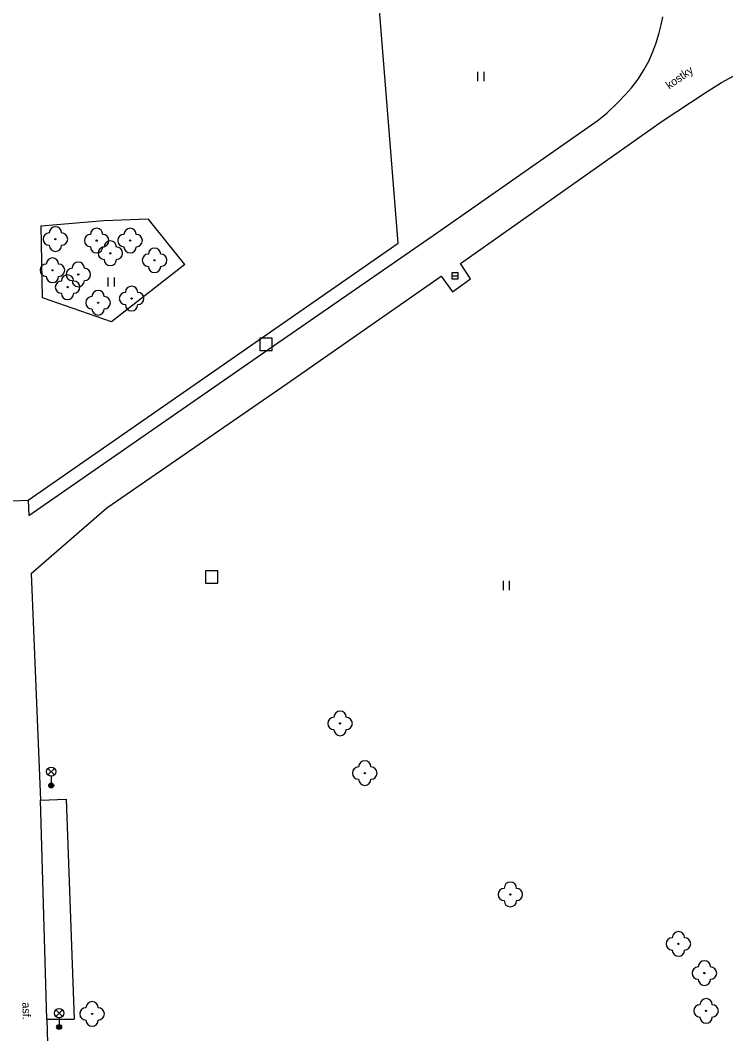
# Model space of a CAD drawing. Extents: x -641829 to -641525, y -1114855 to -1114359.
# Drawn here: x -641652.8 to -641595.5, y -1114618.1 to -1114535.8 of the extents above; entities that cross this region are included whole.
import ezdxf

# ---------------------------------------------------------------- set-up
doc = ezdxf.new("R2010")
doc.units = 0
for name, color, linetype in [('Vrstva 10', 7, 'Continuous'), ('Vrstva 11', 7, 'Continuous'), ('Vrstva 22', 7, 'Continuous'), ('Vrstva 26', 7, 'Continuous'), ('Vrstva 27', 7, 'Continuous'), ('Vrstva 33', 7, 'Continuous'), ('Vrstva 36', 7, 'Continuous'), ('Vrstva 40', 7, 'Continuous')]:
    doc.layers.add(name, color=color, linetype=linetype)

msp = doc.modelspace()

# ---------------------------------------------------------------- linework, layer by layer
at = {"layer": 'Vrstva 10'}
for p, q in [((-641622.14, -1114553.93), (-641623.76, -1114533.67)), ((-641651.12, -1114552.53), (-641646.05, -1114552.1)), ((-641646.05, -1114552.1), (-641642.43, -1114551.97)), ((-641639.45, -1114555.68), (-641642.43, -1114551.97)), ((-641651.01, -1114558.37), (-641651.12, -1114552.53)), ((-641652.17, -1114574.8), (-641622.14, -1114553.93)), ((-641639.45, -1114555.68), (-641645.42, -1114560.33)), ((-641645.42, -1114560.33), (-641651.01, -1114558.37)), ((-641655.53, -1114574.94), (-641652.17, -1114574.8))]:
    msp.add_line(p, q, dxfattribs=at)
at = {"layer": 'Vrstva 11'}
for p, q in [((-641600.78, -1114536.22), (-641600.64, -1114535.57)), ((-641600.93, -1114536.85), (-641600.78, -1114536.22)), ((-641601.19, -1114537.75), (-641600.93, -1114536.85)), ((-641601.46, -1114538.46), (-641601.19, -1114537.75)), ((-641601.76, -1114539.15), (-641601.46, -1114538.46)), ((-641602.64, -1114540.61), (-641602.21, -1114539.92)), ((-641602.21, -1114539.92), (-641601.76, -1114539.15)), ((-641603.18, -1114541.33), (-641602.64, -1114540.61)), ((-641595.87, -1114540.89), (-641594.56, -1114540.18)), ((-641603.67, -1114541.88), (-641603.18, -1114541.33)), ((-641597.19, -1114541.72), (-641595.87, -1114540.89)), ((-641604.35, -1114542.58), (-641603.67, -1114541.88)), ((-641600.69, -1114544.03), (-641597.19, -1114541.72)), ((-641605.19, -1114543.37), (-641604.35, -1114542.58)), ((-641618.94, -1114553.06), (-641605.89, -1114543.94)), ((-641617.07, -1114555.58), (-641600.69, -1114544.03)), ((-641605.89, -1114543.94), (-641605.19, -1114543.37)), ((-641632.62, -1114562.53), (-641618.94, -1114553.06)), ((-641616.26, -1114556.83), (-641617.07, -1114555.58)), ((-641631.15, -1114565.34), (-641618.63, -1114556.62)), ((-641618.63, -1114556.62), (-641617.72, -1114557.88)), ((-641617.72, -1114557.88), (-641616.26, -1114556.83)), ((-641652.12, -1114576.06), (-641632.62, -1114562.53)), ((-641645.8, -1114575.42), (-641631.15, -1114565.34)), ((-641652.17, -1114574.8), (-641652.12, -1114576.06)), ((-641651.93, -1114580.76), (-641645.8, -1114575.42)), ((-641651.93, -1114580.76), (-641651.19, -1114599.17)), ((-641651.19, -1114599.17), (-641649.1, -1114599.09)), ((-641650.66, -1114616.94), (-641651.19, -1114599.17)), ((-641649.1, -1114599.09), (-641648.45, -1114616.94)), ((-641650.66, -1114616.94), (-641650.62, -1114618.87)), ((-641650.66, -1114616.94), (-641648.45, -1114616.94))]:
    msp.add_line(p, q, dxfattribs=at)
at = {"layer": 'Vrstva 22'}
for centre in [(-641649.97, -1114553.61), (-641646.62, -1114553.73), (-641643.9, -1114553.73), (-641645.51, -1114554.76), (-641641.92, -1114555.33), (-641650.21, -1114556.14), (-641648.11, -1114556.48), (-641648.98, -1114557.51), (-641646.5, -1114558.77), (-641643.78, -1114558.43), (-641626.85, -1114592.93), (-641624.84, -1114596.96), (-641613.02, -1114606.82), (-641599.37, -1114610.83), (-641597.26, -1114613.2), (-641597.12, -1114616.27), (-641646.99, -1114616.52)]:
    msp.add_circle(centre, 0.05, dxfattribs=at)
for centre, start, end in [((-641649.97, -1114553.11), 0, 180), ((-641646.62, -1114553.23), 0, 180), ((-641643.9, -1114553.23), 0, 180), ((-641650.47, -1114553.61), 90, 270), ((-641649.47, -1114553.61), 270, 90), ((-641647.12, -1114553.73), 90, 270), ((-641646.12, -1114553.73), 270, 90), ((-641645.51, -1114554.26), 0, 180), ((-641644.4, -1114553.73), 90, 270), ((-641643.4, -1114553.73), 270, 90), ((-641649.97, -1114554.11), 180, 0), ((-641646.62, -1114554.23), 180, 0), ((-641646.01, -1114554.76), 90, 270), ((-641645.01, -1114554.76), 270, 90), ((-641643.9, -1114554.23), 180, 0), ((-641641.92, -1114554.83), 0, 180), ((-641650.21, -1114555.64), 0, 180), ((-641648.11, -1114555.98), 0, 180), ((-641645.51, -1114555.26), 180, 0), ((-641642.42, -1114555.33), 90, 270), ((-641641.42, -1114555.33), 270, 90), ((-641650.71, -1114556.14), 90, 270), ((-641649.71, -1114556.14), 270, 90), ((-641648.61, -1114556.48), 90, 270), ((-641647.61, -1114556.48), 270, 90), ((-641641.92, -1114555.83), 180, 0), ((-641650.21, -1114556.64), 180, 0), ((-641649.48, -1114557.51), 90, 270), ((-641648.98, -1114557.01), 0, 180), ((-641648.11, -1114556.98), 180, 0), ((-641648.48, -1114557.51), 270, 90), ((-641648.98, -1114558.01), 180, 0), ((-641646.5, -1114558.27), 0, 180), ((-641644.28, -1114558.43), 90, 270), ((-641643.78, -1114557.93), 0, 180), ((-641643.28, -1114558.43), 270, 90), ((-641647, -1114558.77), 90, 270), ((-641646, -1114558.77), 270, 90), ((-641646.5, -1114559.27), 180, 0), ((-641643.78, -1114558.93), 180, 0), ((-641627.35, -1114592.93), 90, 270), ((-641626.85, -1114592.43), 0, 180), ((-641626.35, -1114592.93), 270, 90), ((-641626.85, -1114593.43), 180, 0), ((-641625.34, -1114596.96), 90, 270), ((-641624.84, -1114596.46), 0, 180), ((-641624.34, -1114596.96), 270, 90), ((-641624.84, -1114597.46), 180, 0), ((-641613.52, -1114606.82), 90, 270), ((-641613.02, -1114606.32), 0, 180), ((-641612.52, -1114606.82), 270, 90), ((-641613.02, -1114607.32), 180, 0), ((-641599.37, -1114610.33), 0, 180), ((-641599.87, -1114610.83), 90, 270), ((-641598.87, -1114610.83), 270, 90), ((-641599.37, -1114611.33), 180, 0), ((-641597.26, -1114612.7), 0, 180), ((-641597.76, -1114613.2), 90, 270), ((-641596.76, -1114613.2), 270, 90), ((-641597.26, -1114613.7), 180, 0), ((-641646.99, -1114616.02), 0, 180), ((-641597.12, -1114615.77), 0, 180), ((-641647.49, -1114616.52), 90, 270), ((-641646.49, -1114616.52), 270, 90), ((-641597.62, -1114616.27), 90, 270), ((-641596.62, -1114616.27), 270, 90), ((-641646.99, -1114617.02), 180, 0), ((-641597.12, -1114616.77), 180, 0)]:
    msp.add_arc(centre, 0.5, start, end, dxfattribs=at)
at = {"layer": 'Vrstva 26'}
for points in [[(-641633.36, -1114562.65), (-641632.36, -1114562.65), (-641632.36, -1114561.65), (-641633.36, -1114561.65)], [(-641637.79, -1114581.54), (-641636.79, -1114581.54), (-641636.79, -1114580.54), (-641637.79, -1114580.54)]]:
    msp.add_lwpolyline(points, close=True, dxfattribs=at)
at = {"layer": 'Vrstva 27'}
msp.add_line((-641617.76, -1114556.59), (-641617.26, -1114556.59), dxfattribs=at)
msp.add_lwpolyline([(-641617.76, -1114556.84), (-641617.26, -1114556.84), (-641617.26, -1114556.34), (-641617.76, -1114556.34)], close=True, dxfattribs=at)
at = {"layer": 'Vrstva 33'}
for p, q in [((-641650.574, -1114597.11), (-641650.046, -1114596.58)), ((-641650.574, -1114596.58), (-641650.046, -1114597.11)), ((-641650.31, -1114597.22), (-641650.31, -1114597.97)), ((-641649.936, -1114616.72), (-641649.404, -1114616.19)), ((-641649.936, -1114616.19), (-641649.404, -1114616.72)), ((-641649.67, -1114616.83), (-641649.67, -1114617.58))]:
    msp.add_line(p, q, dxfattribs=at)
for centre, radius in [((-641650.31, -1114596.845), 0.375), ((-641650.31, -1114597.97), 0.2), ((-641650.31, -1114597.97), 0.145), ((-641650.31, -1114597.97), 0.0876), ((-641649.67, -1114616.455), 0.375), ((-641649.67, -1114617.58), 0.2), ((-641649.67, -1114617.58), 0.145), ((-641649.67, -1114617.58), 0.0876)]:
    msp.add_circle(centre, radius, dxfattribs=at)
at = {"layer": 'Vrstva 36'}
for p, q in [((-641615.654, -1114540.774), (-641615.654, -1114540.022)), ((-641615.154, -1114540.774), (-641615.154, -1114540.022)), ((-641645.674, -1114557.464), (-641645.674, -1114556.712)), ((-641645.174, -1114557.464), (-641645.174, -1114556.712)), ((-641613.584, -1114582.102), (-641613.584, -1114581.354)), ((-641613.084, -1114582.102), (-641613.084, -1114581.354))]:
    msp.add_line(p, q, dxfattribs=at)

# ---------------------------------------------------------------- texts
at = {"layer": 'Vrstva 40'}
for s, rotation, p in [('kostky', 35.18874, (-641600.11, -1114541.46)), ('asf.', 271.84175, (-641652.66, -1114615.59))]:
    msp.add_text(s, height=0.65, rotation=rotation, dxfattribs=at).set_placement(p)

doc.saveas('drawing.dxf')
